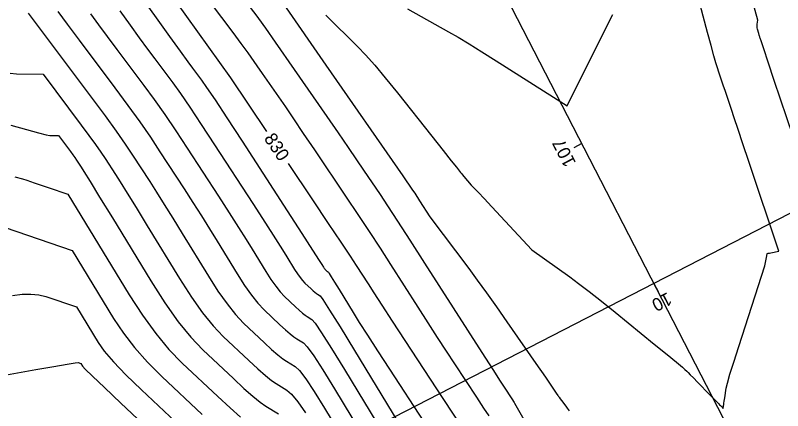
# Model space of a CAD drawing. Extents: x 1715724 to 1716561, y 394063 to 395906.
# Drawn here: x 1715987.4 to 1716070.7, y 395046 to 395089 of the extents above; entities that cross this region are included whole.
import ezdxf

# ---------------------------------------------------------------- set-up
doc = ezdxf.new("R2010")
doc.units = 0
for name, color, linetype in [('DT_X_Contour_Major', 7, 'Continuous'), ('DT_X_Contour_Minor', 7, 'Continuous'), ('GE_P_CL_10', 7, 'Continuous')]:
    doc.layers.add(name, color=color, linetype=linetype)

msp = doc.modelspace()

# ---------------------------------------------------------------- linework, layer by layer
at = {"layer": 'DT_X_Contour_Major'}
for points in [[(1716001.23, 395095.511), (1716010.772, 395082.181), (1716010.777, 395082.174), (1716014.7, 395076.333)], [(1715988.812, 395089.196), (1715995.777, 395079.903), (1715997.17, 395078.026), (1715998.364, 395076.378), (1715999.36, 395074.959), (1716000.156, 395073.768), (1716002.016, 395070.897), (1716002.759, 395069.738), (1716003.594, 395068.412), (1716004.521, 395066.92), (1716005.54, 395065.262), (1716008.38, 395060.62), (1716009.418, 395058.997), (1716010.402, 395057.609), (1716011.33, 395056.457), (1716012.204, 395055.54), (1716014.463, 395053.409), (1716015.248, 395052.683), (1716015.909, 395052.104), (1716016.446, 395051.671), (1716016.859, 395051.385), (1716017.797, 395050.818), (1716018.259, 395050.376), (1716018.944, 395049.477), (1716019.851, 395048.121), (1716020.981, 395046.306), (1716024.291, 395040.859)], [(1716030.006, 395089.645), (1716034.437, 395087.17), (1716035.474, 395086.575), (1716036.685, 395085.852), (1716038.071, 395085), (1716039.63, 395084.018), (1716047.315, 395079.139), (1716051.482, 395087.48), (1716052.267, 395089.051)], [(1716017.041, 395072.846), (1716019.674, 395068.925), (1716021.395, 395066.359), (1716022.761, 395064.312), (1716023.772, 395062.785), (1716024.429, 395061.776), (1716025.708, 395059.78), (1716026.319, 395058.832), (1716027.196, 395057.486), (1716028.336, 395055.74), (1716033.841, 395047.347), (1716036.153, 395043.821)], [(1715987.121, 395058.521), (1715988.166, 395058.663), (1715989.117, 395058.694), (1715989.972, 395058.615), (1715990.732, 395058.426), (1715994.057, 395057.283), (1715996.411, 395053.434), (1715997.084, 395052.494), (1715998.091, 395051.326), (1715999.433, 395049.929), (1716001.111, 395048.302), (1716006.031, 395043.66)]]:
    msp.add_lwpolyline(points, dxfattribs=at)
at = {"layer": 'DT_X_Contour_Minor'}
for points in [[(1716071.829, 395075.811), (1716069.799, 395081.874), (1716069.132, 395083.867), (1716068.653, 395085.299), (1716068.361, 395086.17), (1716068.258, 395086.479), (1716068.232, 395086.557), (1716068.217, 395086.605), (1716068.193, 395086.689), (1716068.16, 395086.811), (1716068.117, 395086.969), (1716067.991, 395087.441), (1716067.952, 395087.608), (1716067.929, 395087.755), (1716067.923, 395087.882), (1716067.933, 395087.99), (1716068.019, 395088.444), (1716063.869, 395103.436)], [(1715998.446, 395094.641), (1716002.724, 395088.664), (1716004.173, 395086.643), (1716005.313, 395085.059), (1716006.143, 395083.914), (1716006.663, 395083.208), (1716007.637, 395081.908), (1716008.186, 395081.128), (1716009.101, 395079.763), (1716010.382, 395077.814), (1716012.03, 395075.279), (1716016.914, 395067.74), (1716018.524, 395065.253), (1716019.691, 395063.449), (1716020.416, 395062.327), (1716020.698, 395061.886), (1716020.861, 395061.62), (1716020.92, 395061.527), (1716020.976, 395061.448), (1716021.029, 395061.382), (1716021.079, 395061.33), (1716021.209, 395061.208), (1716021.254, 395061.166), (1716021.291, 395061.133), (1716021.322, 395061.108), (1716021.346, 395061.092), (1716021.399, 395061.059), (1716021.488, 395060.932), (1716021.713, 395060.575), (1716022.075, 395059.987), (1716022.573, 395059.169), (1716024.085, 395056.68), (1716024.757, 395055.596), (1716025.638, 395054.209), (1716026.729, 395052.52), (1716028.03, 395050.528), (1716031.779, 395044.813)], [(1716006.106, 395093.638), (1716011.026, 395087.079), (1716011.911, 395085.897), (1716012.461, 395085.16), (1716012.676, 395084.869), (1716013.639, 395083.482), (1716014.225, 395082.637), (1716015.992, 395080.089), (1716016.733, 395079.013), (1716017.63, 395077.696), (1716018.685, 395076.137), (1716019.896, 395074.338), (1716023.335, 395069.217), (1716024.603, 395067.32), (1716025.826, 395065.468), (1716027.006, 395063.662), (1716028.141, 395061.902), (1716031.108, 395057.27), (1716032.193, 395055.581), (1716033.221, 395053.989), (1716034.192, 395052.493), (1716035.106, 395051.095), (1716037.468, 395047.494), (1716038.245, 395046.308), (1716038.807, 395045.451)], [(1716021.13, 395088.983), (1716024.611, 395085.543), (1716025.438, 395084.678), (1716026.428, 395083.556), (1716027.581, 395082.178), (1716028.897, 395080.543), (1716032.623, 395075.843), (1716033.853, 395074.291), (1716034.746, 395073.163), (1716035.304, 395072.459), (1716035.527, 395072.177), (1716035.741, 395071.904), (1716035.837, 395071.785), (1716035.961, 395071.633), (1716036.112, 395071.447), (1716036.883, 395070.505), (1716037.147, 395070.273), (1716037.314, 395070.104), (1716037.699, 395069.698), (1716038.304, 395069.054), (1716039.129, 395068.172), (1716043.488, 395063.5), (1716047.593, 395060.557), (1716048.561, 395059.844), (1716049.706, 395058.964), (1716051.028, 395057.92), (1716052.526, 395056.709), (1716056.756, 395053.26), (1716058.155, 395052.119), (1716059.176, 395051.28), (1716059.821, 395050.745), (1716060.09, 395050.513), (1716060.304, 395050.298), (1716060.436, 395050.164), (1716060.673, 395049.923), (1716061.015, 395049.575), (1716061.46, 395049.119), (1716062.788, 395047.762), (1716063.228, 395047.313), (1716063.553, 395046.982), (1716063.761, 395046.769), (1716063.854, 395046.675), (1716063.946, 395046.582), (1716063.981, 395046.547), (1716064.016, 395046.512), (1716064.05, 395046.476), (1716064.085, 395046.44), (1716064.247, 395046.272), (1716064.281, 395046.508), (1716064.288, 395046.553), (1716064.293, 395046.586), (1716064.297, 395046.608), (1716064.299, 395046.618), (1716064.302, 395046.629), (1716064.311, 395046.681), (1716064.334, 395046.83), (1716064.373, 395047.075), (1716064.427, 395047.416), (1716064.59, 395048.454), (1716064.72, 395049.03), (1716064.987, 395049.978), (1716065.392, 395051.298), (1716065.933, 395052.992), (1716068.781, 395061.762), (1716068.941, 395062.658), (1716068.972, 395062.827), (1716068.996, 395062.95), (1716069.013, 395063.028), (1716069.023, 395063.06), (1716069.04, 395063.086), (1716069.069, 395063.098), (1716069.143, 395063.117), (1716069.261, 395063.141), (1716069.425, 395063.172), (1716070.295, 395063.328), (1716067.034, 395073.072), (1716066.391, 395074.99), (1716065.862, 395076.571), (1716065.447, 395077.813), (1716065.144, 395078.717), (1716064.488, 395080.677), (1716064.262, 395081.353), (1716064.075, 395081.911), (1716063.928, 395082.351), (1716063.82, 395082.673), (1716063.586, 395083.374), (1716063.455, 395083.804), (1716063.239, 395084.567), (1716062.939, 395085.665), (1716062.553, 395087.096), (1716061.41, 395091.359)], [(1716012.571, 395090.256), (1716013.624, 395088.848), (1716014.295, 395087.948), (1716014.582, 395087.556), (1716015.644, 395086.025), (1716017.683, 395083.085), (1716021.222, 395077.982), (1716022.468, 395076.183), (1716023.549, 395074.611), (1716024.467, 395073.268), (1716025.222, 395072.152), (1716027.015, 395069.482), (1716027.822, 395068.265), (1716028.897, 395066.617), (1716030.24, 395064.538), (1716031.852, 395062.028), (1716038.066, 395052.33), (1716039.246, 395050.492), (1716040.047, 395049.247), (1716040.47, 395048.593), (1716041.303, 395047.322), (1716041.566, 395046.915), (1716041.62, 395046.826), (1716043.762, 395043.023)], [(1716016.488, 395090.243), (1716021.141, 395083.534), (1716029.468, 395071.526), (1716030.547, 395069.967), (1716030.773, 395069.628), (1716031.29, 395068.826), (1716032.42, 395067.061), (1716036.629, 395061.47), (1716037.565, 395060.209), (1716038.569, 395058.822), (1716039.642, 395057.311), (1716040.784, 395055.673), (1716043.919, 395051.14), (1716044.95, 395049.649), (1716045.69, 395048.577), (1716046.14, 395047.925), (1716046.3, 395047.691), (1716046.338, 395047.626), (1716046.372, 395047.577), (1716046.445, 395047.476), (1716046.557, 395047.326), (1716046.708, 395047.124), (1716047.162, 395046.519), (1716047.317, 395046.31), (1716047.444, 395046.137), (1716047.542, 395046.001)], [(1715992.028, 395089.372), (1715993.047, 395088.004), (1715994.359, 395086.252), (1715998.247, 395081.064), (1715999.646, 395079.173), (1716000.925, 395077.389), (1716002.084, 395075.714), (1716003.125, 395074.146), (1716005.74, 395070.108), (1716006.7, 395068.617), (1716007.618, 395067.171), (1716008.495, 395065.772), (1716009.33, 395064.418), (1716011.501, 395060.87), (1716012.294, 395059.629), (1716013.045, 395058.569), (1716013.755, 395057.688), (1716014.423, 395056.987), (1716016.149, 395055.359), (1716016.749, 395054.804), (1716017.255, 395054.361), (1716017.665, 395054.031), (1716017.981, 395053.812), (1716018.697, 395053.378), (1716019.109, 395052.945), (1716019.808, 395051.97), (1716020.793, 395050.453), (1716022.065, 395048.394), (1716025.838, 395042.181)], [(1715995.591, 395089.117), (1715996.456, 395087.934), (1715997.413, 395086.641), (1715998.461, 395085.237), (1716001.377, 395081.346), (1716002.492, 395079.825), (1716003.65, 395078.181), (1716004.85, 395076.414), (1716006.093, 395074.523), (1716009.465, 395069.318), (1716010.641, 395067.496), (1716011.643, 395065.931), (1716012.469, 395064.623), (1716013.119, 395063.574), (1716014.621, 395061.12), (1716015.169, 395060.262), (1716015.689, 395059.528), (1716016.18, 395058.919), (1716016.642, 395058.435), (1716017.836, 395057.308), (1716018.251, 395056.925), (1716018.6, 395056.618), (1716018.884, 395056.39), (1716019.103, 395056.239), (1716019.598, 395055.939), (1716019.959, 395055.513), (1716020.671, 395054.462), (1716021.734, 395052.784), (1716023.148, 395050.481), (1716027.386, 395043.504)], [(1715998.771, 395089.427), (1715999.882, 395087.88), (1716000.885, 395086.497), (1716001.778, 395085.278), (1716002.562, 395084.222), (1716004.507, 395081.627), (1716005.339, 395080.476), (1716006.375, 395078.972), (1716007.616, 395077.114), (1716009.062, 395074.901), (1716013.189, 395068.529), (1716014.582, 395066.375), (1716015.667, 395064.69), (1716016.442, 395063.475), (1716016.909, 395062.73), (1716017.741, 395061.37), (1716018.045, 395060.895), (1716018.333, 395060.488), (1716018.605, 395060.151), (1716018.861, 395059.882), (1716019.522, 395059.258), (1716019.752, 395059.045), (1716019.946, 395058.876), (1716020.103, 395058.749), (1716020.224, 395058.665), (1716020.499, 395058.499), (1716020.809, 395058.082), (1716021.535, 395056.954), (1716022.676, 395055.116), (1716024.232, 395052.568), (1716028.934, 395044.827)], [(1715986.882, 395082.67), (1715987.565, 395082.617), (1715990.456, 395082.546), (1715994.589, 395077.031), (1715995.415, 395075.917), (1715996.124, 395074.939), (1715996.715, 395074.097), (1715997.188, 395073.39), (1715998.291, 395071.687), (1715998.818, 395070.859), (1715999.57, 395069.653), (1716000.547, 395068.069), (1716001.751, 395066.107), (1716005.26, 395060.37), (1716006.543, 395058.364), (1716007.758, 395056.649), (1716008.905, 395055.225), (1716009.986, 395054.092), (1716012.776, 395051.459), (1716013.746, 395050.562), (1716014.563, 395049.847), (1716015.227, 395049.312), (1716015.738, 395048.959), (1716016.896, 395048.258), (1716017.409, 395047.808), (1716018.08, 395046.985), (1716018.91, 395045.789)], [(1715986.947, 395077.016), (1715988.657, 395076.539), (1715989.934, 395076.197), (1715990.778, 395075.989), (1715991.19, 395075.917), (1715992.1, 395075.895), (1715993.401, 395074.159), (1715993.661, 395073.808), (1715993.884, 395073.5), (1715994.07, 395073.235), (1715994.219, 395073.012), (1715994.567, 395072.476), (1715994.876, 395071.98), (1715995.545, 395070.894), (1715996.574, 395069.217), (1715997.961, 395066.951), (1716002.14, 395060.12), (1716003.667, 395057.731), (1716005.114, 395055.689), (1716006.481, 395053.994), (1716007.767, 395052.645), (1716011.09, 395049.51), (1716012.245, 395048.442), (1716013.218, 395047.589), (1716014.008, 395046.953), (1716014.616, 395046.532), (1716015.995, 395045.697)], [(1715987.384, 395071.43), (1715988.192, 395071.191), (1715988.666, 395071.044), (1715989.483, 395070.77), (1715989.807, 395070.661), (1715990.566, 395070.404), (1715991, 395070.255), (1715993.111, 395069.529), (1715999.793, 395058.607), (1716001.227, 395056.388), (1716002.664, 395054.414), (1716004.104, 395052.684), (1716005.548, 395051.197), (1716009.403, 395047.56), (1716010.743, 395046.321), (1716011.872, 395045.332)], [(1715986.33, 395065.898), (1715993.584, 395063.406), (1715998.102, 395056.02), (1715999.155, 395054.441), (1716000.377, 395052.87), (1716001.769, 395051.306), (1716003.329, 395049.75), (1716007.717, 395045.61)], [(1715983.662, 395049.401), (1715989.651, 395050.482), (1715991.624, 395050.834), (1715993.05, 395051.08), (1715993.928, 395051.219), (1715994.259, 395051.253), (1715994.529, 395051.16), (1715994.721, 395050.847), (1715995.012, 395050.547), (1715995.805, 395049.782), (1715997.098, 395048.551), (1715998.892, 395046.855), (1716004.344, 395041.711)]]:
    msp.add_lwpolyline(points, dxfattribs=at)
at = {"layer": 'GE_P_CL_10'}
for p, q in [((1716249.46, 394685.42), (1715852.538, 395456.564)), ((1716111.51, 395088.045), (1715997.389, 395029.305)), ((1716048.922, 395075.029), (1716048.033, 395074.571)), ((1716056.732, 395059.85), (1716057.19, 395058.961))]:
    msp.add_line(p, q, dxfattribs=at)

# ---------------------------------------------------------------- texts
at = {"layer": 'DT_X_Contour_Major'}
msp.add_text('830', height=1.4, rotation=303.88156, dxfattribs=at).set_placement((1716014.361, 395075.581))
at = {"layer": 'GE_P_CL_10'}
for s, rotation, p in [('107', 117.23573, (1716048.307, 395072.946)), ('10', 207.23573, (1716058.207, 395058.922))]:
    msp.add_text(s, height=1.4, rotation=rotation, dxfattribs=at).set_placement(p)

doc.saveas('drawing.dxf')
